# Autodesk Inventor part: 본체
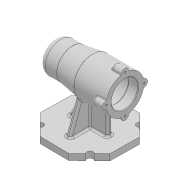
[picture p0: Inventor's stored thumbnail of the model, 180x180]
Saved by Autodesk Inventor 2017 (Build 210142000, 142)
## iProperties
Created: 2019-12
Part Number: 본체
Material: Generic
Document SubType Name: Modeling
Designer: 5-02-le
Density: 1 g/cm^3
Appearance: Default
Author: 5-02-le
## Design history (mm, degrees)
sketch "스케치2"
  geometry: L1 (23.927, 55.692)-(56.299, 22.461); L2 (56.299, 22.461)-(55.692, -23.927); L3 (55.692, -23.927)-(22.461, -56.299); L4 (22.461, -56.299)-(-23.927, -55.692); L5 (-23.927, -55.692)-(-56.299, -22.461); L6 (-56.299, -22.461)-(-55.692, 23.927); L7 (-55.692, 23.927)-(-22.461, 56.299); L8 (-22.461, 56.299)-(23.927, 55.692); 2 further points
  constraints: 16 end point, 17 other
  dimensions: "d1" = 56 distance from line of L2 point (0, 0)
extrude "돌출1" new body sketch "스케치2" stored distance "d2" = 10; taper "d3" = 0 deg
sketch "스케치3"
  geometry: L1 (56.299, 75)-(-55.701, 75); L2 (56.299, 5)-(56.299, -5) reference; L3 (-55.692, -5)-(-22.461, -5) reference; L4 (56.299, 75)-(56.299, 100); L5 (56.299, 100)-(27.912, 100); L6 (27.912, 100)-(-4.425, 105); L7 (-55.701, 75)-(-55.701, 105); L8 (-4.425, 105)-(-55.701, 105); 1 further point
  constraints: 12 end point, 2 horizontal, 2 vertical, 1 perpendicular, 1 point on line
  dimensions: "d4" = 80 distance between parallel lines of L3 L1; "d5" = 50 diameter of L5 L1; "d6" = 60 diameter of L8 L1; "d7" = 112 distance between parallel lines of L7 L4
revolve "회전1" sketch "스케치3" stored, may be unused: angle "d8" = 90 deg
sketch "스케치4"
  geometry: L1 (30.692, 5)-(10.133, 49.089); L2 (10.133, 49.089)-(-31.299, 49.089); L3 (-31.299, 49.089)-(-31.299, 5); L4 (-31.299, 5)-(30.692, 5); L5 (55.692, 5)-(55.692, -5) reference; L6 (-56.299, 5)-(-56.299, -5) reference; L7 (22.461, 5)-(55.692, 5) reference; 1 further point
  constraints: 8 end point, 2 perpendicular
  dimensions: "d9" = 25 distance from line of L1.start L5; "d10" = 25 distance from line of L6 L3.end; "d11" = 115 deg angle of L7 L1
extrude "돌출2" join sketch "스케치4" stored distance "d12" = 8; taper "d13" = 0 deg
sketch "스케치5"
  geometry: L1 (-35.692, 5)-(-17.068, 56.167); L2 (-17.068, 56.167)-(17.675, 56.167); L3 (17.675, 56.167)-(36.299, 5); L4 (56.299, 5)-(23.927, 5) reference; L5 (-35.692, 5)-(36.299, 5); L6 (-22.461, 5)-(-55.692, 5) reference; L7 (-55.692, 5)-(-55.692, -5) reference; L8 (56.299, 5)-(56.299, -5) reference; 1 further point
  constraints: 8 end point, 1 collinear, 1 horizontal, 1 point on line
  dimensions: "d14" = 20 distance from line of L7 L1.start; "d15" = 20 distance from line of L8 L3.end; "d16" = 110 deg angle of L4 L3; "d17" = 110 deg angle of L1 L6
extrude "돌출3" join sketch "스케치5" stored distance "d18" = 8; taper "d19" = 0 deg
sketch "스케치6"
  geometry: L1 (56.299, 50)-(56.299, 100) reference; L2 (56.299, 75)-(-57.001, 75); L3 (50.299, 75)-(47.299, 75); L4 (47.299, 75)-(47.299, 85.5); L5 (47.299, 85.5)-(50.299, 85.5); L6 (50.299, 85.5)-(50.299, 75); L7 (47.299, 75)-(43.299, 75); L8 (43.299, 75)-(43.299, 91); L9 (43.299, 91)-(47.299, 91); L10 (47.299, 91)-(47.299, 75); L11 (43.299, 75)-(25.299, 75); L12 (25.299, 75)-(25.299, 92.5); L13 (25.299, 92.5)-(43.299, 92.5); L14 (43.299, 92.5)-(43.299, 75); L15 (25.299, 75)-(13.299, 75); L16 (13.299, 75)-(13.299, 96); L17 (13.299, 96)-(25.299, 96); L18 (25.299, 96)-(25.299, 75); L19 (13.299, 75)-(-40.701, 75); L20 (-40.701, 75)-(-40.701, 99); L21 (-40.701, 99)-(13.299, 99); L22 (13.299, 99)-(13.299, 75); L23 (-40.701, 75)-(-55.701, 75); L24 (-40.701, 92.5)-(-40.701, 75); L25 (-55.701, 45)-(-55.701, 105) reference; L26 (-40.701, 75)-(-55.701, 75); L27 (-55.701, 75)-(-55.701, 96); L28 (-55.701, 96)-(-40.701, 96); L29 (-40.701, 96)-(-40.701, 75); 1 further point
  constraints: 54 end point, 12 parallel, 7 horizontal, 6 perpendicular, 2 point on line, 1 midpoint
  dimensions: "d20" = 3 distance between parallel lines of L4 L6; "d21" = 4 distance between parallel lines of L8 L10; "d22" = 18 distance between parallel lines of L18 L14; "d23" = 12 distance between parallel lines of L22 L18; "d24" = 54 distance between parallel lines of L20 L22; "d26" = 21 diameter of L5 L2; "d27" = 32 diameter of L9 L2; "d28" = 35 diameter of L13 L2; "d29" = 42 diameter of L17 L2; "d30" = 48 diameter of L21 L2; "d32" = 42 diameter of L28 L2; "d33" = 15 distance between parallel lines of L25 L20
revolve "회전2" sketch "스케치6" stored, may be unused: angle "d34" = 90 deg
sketch "스케치7"
  geometry: L1 (0, 0)-(-30, 0); C1 r 6 at (-30, 0); 1 further point
  constraints: 2 end point, 1 centre point, 1 coincident, 1 horizontal
  dimensions: "d35" = 12 diameter of C1
extrude "돌출4" join sketch "스케치7" distance "d36" = 16; taper "d37" = 0 deg
fillet "모깎기1" dims "d38" = 3
fillet "모깎기2" dims "d39" = 1
sketch "스케치8" dims "d4" = 80, "d5" = 50, "d6" = 60, "d7" = 112
  geometry: 2 further points
hole "구멍1" sketch "스케치8" at (0, -0.048) diameter "d43" = 3.242; stored, may be unused: countersink angle "d47" = 90 deg, drill point angle "d49" = 118 deg; dims "d44" = 8, "d45" = 4, "d46" = 2, "d48" = 11.8
sketch "스케치9"
  geometry: 1 further point
sketch "스케치10"
  geometry: L1 (0, 0)-(-39.601, 39.601); L2 (0, 0)-(-39.601, -39.601); L3 (0, 0)-(39.601, 39.601); L4 (0, 0)-(39.601, -39.601); L5 (0, 0)-(0, 56.005); C1 r 5 at (-39.601, 39.601); C2 r 5 at (-39.601, -39.601); C3 r 5 at (39.601, 39.601); C4 r 5 at (39.601, -39.601)
  constraints: 10 end point, 4 centre point, 4 coincident, 1 vertical
  dimensions: "d54" = 10 diameter of C1; "d56" = 90 deg angle of L1 L2; "d57" = 10 diameter of C2; "d58" = 45 deg angle of L3 L5; "d59" = 90 deg angle of L4 L3; "d60" = 10 diameter of C4; "d61" = 10 diameter of C3
extrude "돌출5" cut sketch "스케치10" stored distance "d62" = 16; taper "d63" = 0 deg
fillet "모깎기3" dims "d64" = 10
fillet "모깎기4" dims "d65" = 1
fillet "모깎기5" dims "d66" = 3
fillet "모깎기6" dims "d67" = 3
fillet "모깎기7" dims "d68" = 3
chamfer "모따기1" distance "d69" = 1; stored, may be unused: second distance "d70" = 2, angle "d71" = 45 deg
fillet "모깎기8" dims "d72" = 0.3
fillet "모깎기9" dims "d73" = 3
node "솔리드1"
pattern_circular "원형 패턴1" dims angle "d41" = 360 deg
pattern_circular "원형 패턴2" dims angle "d51" = 360 deg
